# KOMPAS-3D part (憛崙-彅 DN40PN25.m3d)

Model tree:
1. Объединить компоненты:1  (labels: СЕНС-ПФ DN40PN25)

Referenced files in D:\Савин\!СЕНСОР\3D для заказчика\!Новый перечень\СЕНС-ПФ\DN40\: СЕНС-ПФ DN40PN25.a3d
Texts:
  СЕНС-ПФ DN40PN25
  ООО НПП Сенсор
